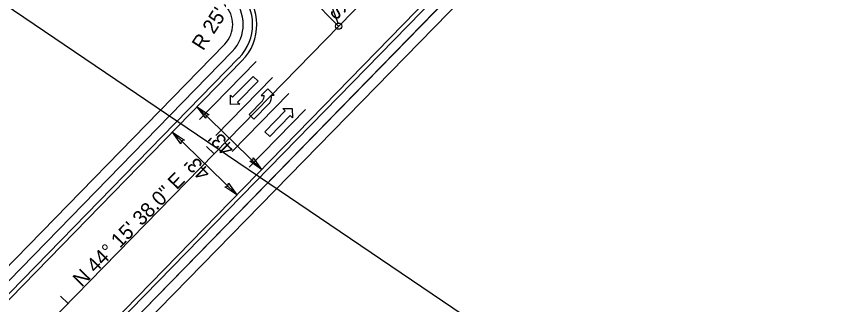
# Model space of a CAD drawing. Extents: x 1974386 to 1979988, y 776712 to 784860.
# Drawn here: x 1976659.3 to 1977051.5, y 779824.2 to 779962.3 of the extents above; entities that cross this region are included whole.
import ezdxf

# ---------------------------------------------------------------- set-up
doc = ezdxf.new("R2010")
doc.units = 0
for name, color, linetype in [('Prop Conc 2ft 6in Curb and Gutter', 7, 'Continuous'), ('Prop Conc 4in Sidewalk', 7, 'Continuous'), ('Prop Dimension', 7, 'Continuous'), ('Prop Dimension Text', 7, 'Continuous'), ('Prop EOT', 7, 'Continuous'), ('Prop Horizontal Alignment', 7, 'Continuous'), ('Prop Horizontal Alignment Direction Label', 7, 'Continuous'), ('Prop Horizontal Alignment Station Label', 7, 'Continuous'), ('Prop Horizontal Alignment Tick Small', 7, 'Continuous'), ('Prop Lane Arrow CELL', 7, 'Continuous'), ('Prop Lane Lines', 7, 'Continuous'), ('Prop Terminator CELL', 7, 'Continuous'), ('Sheet Layout Plan Border', 7, 'Continuous')]:
    doc.layers.add(name, color=color, linetype=linetype)

msp = doc.modelspace()

# ---------------------------------------------------------------- linework, layer by layer
at = {"layer": 'Prop Conc 2ft 6in Curb and Gutter'}
for p, q in [((1976688.32, 779795.62), (1977006.57, 780122.2)), ((1976546.47, 779717.4), (1976765.69, 779942.36))]:
    msp.add_line(p, q, dxfattribs=at)
msp.add_arc((1976749.21, 779958.4), 23, 315.7395, 44.7138, dxfattribs=at)
at = {"layer": 'Prop Conc 4in Sidewalk'}
for p, q in [((1976586.27, 779684.45), (1977009.79, 780119.06)), ((1977009.79, 780119.06), (1976586.27, 779684.45)), ((1976589.85, 779680.96), (1977013.37, 780115.57)), ((1976589.85, 779680.96), (1977013.37, 780115.57))]:
    msp.add_line(p, q, dxfattribs=at)
for points in [[(1976569.28, 779774.25), (1976640.03, 779827.02), (1976758.88, 779948.99)], [(1976758.88, 779948.98), (1976640.03, 779827.02), (1976569.28, 779774.25)], [(1976559.67, 779760.84), (1976643.63, 779823.56), (1976762.46, 779945.49)], [(1976559.67, 779760.84), (1976643.63, 779823.56), (1976762.46, 779945.49)]]:
    msp.add_lwpolyline(points, dxfattribs=at)
for radius in [18.5, 18.5, 13.5, 13.5]:
    msp.add_arc((1976749.21, 779958.4), radius, 315.7395, 44.7243, dxfattribs=at)
at = {"layer": 'Prop Dimension'}
for p, q in [((1976776.54, 779889.02), (1976745.74, 779919.03)), ((1976764.67, 779876.83), (1976733.87, 779906.84))]:
    msp.add_line(p, q, dxfattribs=at)
at = {"layer": 'Prop EOT'}
for p, q in [((1976581.61, 779688.99), (1977005.14, 780123.59)), ((1976550.82, 779719), (1976767.11, 779940.96))]:
    msp.add_line(p, q, dxfattribs=at)
msp.add_arc((1976749.21, 779958.4), 25, 315.7395, 44.7243, dxfattribs=at)
at = {"layer": 'Prop Horizontal Alignment'}
for p, q in [((1976566.21, 779704), (1976989.74, 780138.6)), ((1976719.09, 780052.76), (1976813.35, 779957.59)), ((1976719.09, 780052.76), (1976813.35, 779957.59))]:
    msp.add_line(p, q, dxfattribs=at)
at = {"layer": 'Prop Horizontal Alignment Station Label'}
msp.add_line((1976813.16, 779959.08), (1976757.85, 780107.89), dxfattribs=at)
msp.add_circle((1976813.35, 779957.59), 1.5, dxfattribs=at)
at = {"layer": 'Prop Horizontal Alignment Tick Small'}
for p, q in [((1976753.77, 779896.46), (1976750.19, 779899.95)), ((1976683.98, 779824.84), (1976680.4, 779828.33))]:
    msp.add_line(p, q, dxfattribs=at)
at = {"layer": 'Prop Lane Arrow CELL'}
for p, q in [((1976762.66, 779923.57), (1976772.47, 779933.55)), ((1976772.47, 779933.55), (1976774.83, 779931.24)), ((1976774.83, 779931.24), (1976765.02, 779921.26)), ((1976761.67, 779920.13), (1976761.59, 779924.62)), ((1976761.59, 779924.62), (1976762.66, 779923.57)), ((1976779.48, 779927.61), (1976776.3, 779924.42)), ((1976776.3, 779924.42), (1976777.79, 779924.44)), ((1976782.6, 779924.51), (1976779.48, 779927.61)), ((1976781.11, 779924.49), (1976782.6, 779924.51)), ((1976765.02, 779921.26), (1976766.09, 779920.2)), ((1976776.87, 779921.85), (1976770.49, 779915.29)), ((1976772.86, 779912.98), (1976780.21, 779920.55)), ((1976766.09, 779920.2), (1976761.67, 779920.13)), ((1976778.09, 779907), (1976787.8, 779917.08)), ((1976786.72, 779918.12), (1976791.14, 779918.23)), ((1976787.8, 779917.08), (1976786.72, 779918.12)), ((1976791.14, 779918.23), (1976791.26, 779913.75)), ((1976770.49, 779915.29), (1976772.86, 779912.98)), ((1976790.18, 779914.79), (1976780.46, 779904.71)), ((1976791.26, 779913.75), (1976790.18, 779914.79)), ((1976780.46, 779904.71), (1976778.09, 779907))]:
    msp.add_line(p, q, dxfattribs=at)
for centre, radius, start, end in [((1976774.54, 779924.12), 3.27, 315.8007, 5.4589), ((1976775.95, 779923.59), 5.25, 324.4768, 9.7885)]:
    msp.add_arc(centre, radius, start, end, dxfattribs=at)
at = {"layer": 'Prop Lane Lines'}
for p, q in [((1976746.76, 779912.9), (1976773.86, 779940.71)), ((1976754.63, 779905.22), (1976781.74, 779933.03)), ((1976762.51, 779897.55), (1976789.61, 779925.36)), ((1976770.57, 779890.05), (1976797.49, 779917.68))]:
    msp.add_line(p, q, dxfattribs=at)
at = {"layer": 'Prop Terminator CELL'}
for points in [[(1976749.77, 779913.48), (1976745.74, 779919.03), (1976751.44, 779915.15), (1976749.99, 779914.89)], [(1976737.89, 779901.3), (1976733.87, 779906.84), (1976739.57, 779902.96), (1976738.11, 779902.71)], [(1976737.89, 779901.3), (1976733.87, 779906.84), (1976739.57, 779902.96), (1976738.11, 779902.71)], [(1976772.52, 779894.56), (1976776.54, 779889.02), (1976770.84, 779892.89), (1976772.3, 779893.15)], [(1976760.64, 779882.38), (1976764.67, 779876.83), (1976758.97, 779880.71), (1976760.42, 779880.97)]]:
    msp.add_lwpolyline(points, close=True, dxfattribs=at)
at = {"layer": 'Sheet Layout Plan Border'}
msp.add_lwpolyline([(1976403.86, 778445.65), (1977189.89, 779604.17), (1976321, 780193.69), (1975534.97, 779035.17)], close=True, dxfattribs=at)

# ---------------------------------------------------------------- texts
at = {"layer": 'Prop Dimension Text'}
for s, rotation, p in [("R 25'", 57.255, (1976748.56, 779945.49)), ("43'", 135.361, (1976764.02, 779899.52)), ("43'", 135.361, (1976752.5, 779887.84))]:
    msp.add_text(s, height=7, rotation=rotation, dxfattribs=at).set_placement(p)
at = {"layer": 'Prop Horizontal Alignment Direction Label'}
for s, rotation, p in [('S 44%%d 43\' 27.5" E', 134.7243, (1976817.94, 779964.81)), ('N 44%%d 15\' 38.0" E', 45.7395, (1976690.54, 779832.28))]:
    msp.add_text(s, height=7, rotation=rotation, dxfattribs=at).set_placement(p)

doc.saveas('drawing.dxf')
